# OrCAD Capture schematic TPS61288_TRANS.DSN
size B; title: TPS61288 Pspice Simulation; rev: 1.0
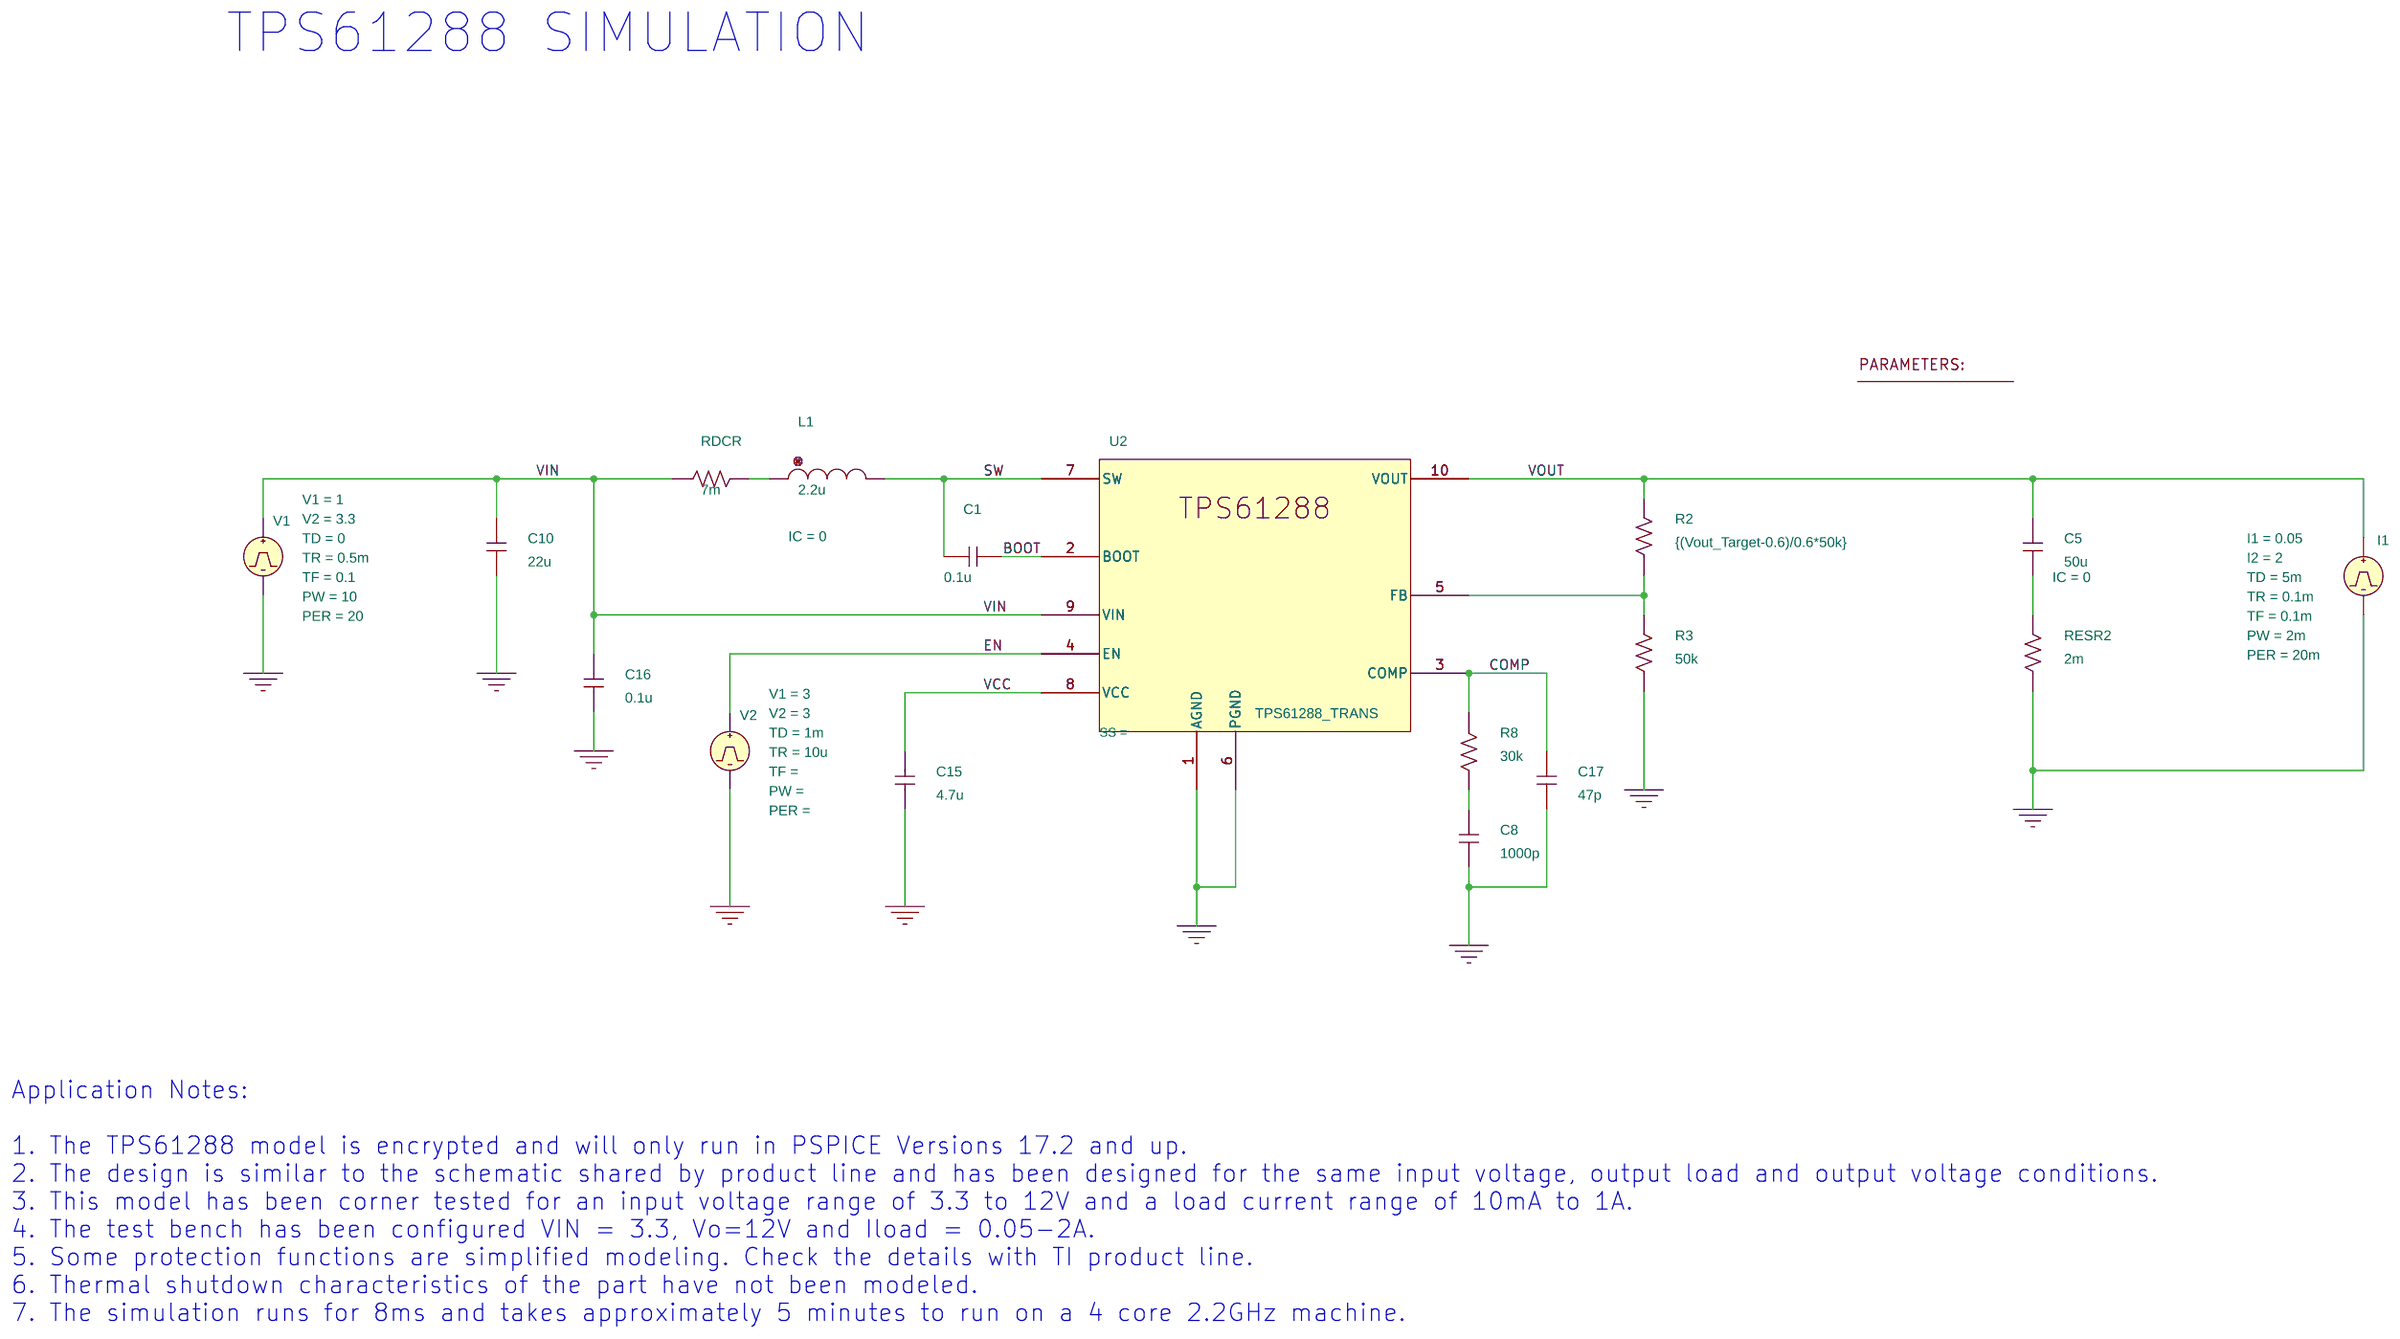
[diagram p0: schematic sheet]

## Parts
1  PARAM
C1  0.1u  [RAD/CK05]
C5  50u  [RAD/CK05]
C8  1000p  [RAD/CK05]
C10  22u  [RAD/CK05]
C15  4.7u  [RAD/CK05]
C16  0.1u  [RAD/CK05]
C17  47p  [RAD/CK05]
I1  IPULSE
L1  2.2u  [DISC/.350x.175/LS.200x.100/.034]
R2  {(Vout_Target-0.6)/0.6*50k}  [AX/RC05]
R3  50k  [AX/RC05]
R8  30k  [AX/RC05]
RDCR  7m  [AX/RC05]
RESR2  2m  [AX/RC05]
U2  TPS61288_TRANS
V1  VPULSE
V2  VPULSE

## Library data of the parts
1 = PARAM: Fast_Startup: 0; SS: 0; Vout_Target: 13
C1 C8 C10 C15-C17 = C
C5 = C: IC: 0
I1 = IPULSE: I1: 0.05; I2: 2; PER: 20m; PW: 2m; TD: 5m; TF: 0.1m; TR: 0.1m
L1 = L: IC: 0
R2 R3 R8 RDCR RESR2 = R
U2 = TPS61288_TRANS_4
V1 = VPULSE: PER: 20; PW: 10; TD: 0; TF: 0.1; TR: 0.5m; V1: 1; V2: 3.3
V2 = VPULSE: TD: 1m; TR: 10u; V1: 3; V2: 3

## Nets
VCC: C15.1 U2.8(VCC)
VIN: C10.2 C16.2 RDCR.1 U2.9(VIN) V1.1(+)
0: C8.2 C10.1 C15.2 C16.1 C17.2 I1.2(-) R3.1 RESR2.1 U2.1(AGND) U2.6(PGND) V1.2(-) V2.2(-)
BOOT: C1.1 U2.2(BOOT)
COMP: C17.1 R8.1 U2.3(COMP)
EN: U2.4(EN) V2.1(+)
SW: C1.2 L1.2 U2.7(SW)
VOUT: C5.1 I1.1(+) R2.2 U2.10(VOUT)
N00101: L1.1 RDCR.2
N24383: C5.2 RESR2.2
N72278: R2.1 R3.2 U2.5(FB)
N99534: C8.1 R8.2

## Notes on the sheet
- TPS61288 SIMULATION
- Application Notes:
  1. The TPS61288 model is encrypted and will only run in PSPICE Versions 17.2 and up.
  2. The design is similar to the schematic shared by product line and has been designed for the same input voltage, output load and output voltage conditions.
  3. This model has been corner tested for an input voltage range of 3.3 to 12V and a load current range of 10mA to 1A.
  4. The test bench has been configured VIN = 3.3, Vo=12V and Iload = 0.05-2A.
  5. Some protection functions are simplified modeling. Check the details with TI product line.
  6. Thermal shutdown characteristics of the part have not been modeled.
  7. The simulation runs for 8ms and takes approximately 5 minutes to run on a 4 core 2.2GHz machine.
